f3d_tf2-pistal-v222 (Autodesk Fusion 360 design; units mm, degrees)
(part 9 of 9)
sketch "Sketch209" plane through (-12, 0, 0) normal (-1, 0, 0) x axis (0, -1, 0)
  line L1 (-152.7089, 8.4519) -> (-152.3198, 8.841)
  line L2 (-153.3679, 3.9459) -> (-153.3679, 6.8609)
  line L3 (-156.6179, 2.4459) -> (-154.8679, 2.4459)
  line L4 (-159.3679, 12.5) -> (-159.3679, 5.1959)
  line L5 (-102, 15.5) -> (-156.3679, 15.5)
  line L6 (-99.5, 12) -> (-99.5, 13)
  line L7 (-150.7288, 9.5) -> (-102, 9.5)
  line L8 (-62.1873, 16) -> (-62.1873, 4.4251)
  line L9 (-205.8331, 16) -> (-62.1873, 16)
  line L10 (-221.2152, 0.6179) -> (-205.8331, 16)
  line L11 (-220.6993, -4.9724) -> (-221.2152, 0.6179)
  line L12 (-206.6662, -17.6022) -> (-220.6993, -4.9724)
  line L13 (-206.6662, -40.176) -> (-206.6662, -17.6022)
  curve K1 (-206.6662, -40.176) -> (-240.3598, -109.3449)
  line L14 (-189.1188, -123.2274) -> (-240.3598, -109.3449)
  line L15 (-186.4094, -113.2266) -> (-189.1188, -123.2274)
  line L16 (-189.1513, -106.0289) -> (-186.4094, -113.2266)
  line L17 (-169.5112, -33.2283) -> (-189.2884, -97.8715)
  curve K2 (-169.5112, -33.2283) -> (-143.7253, -13.6797)
  line L18 (-94.4207, -13.6797) -> (-143.7253, -13.6797)
  curve K3 (-94.4207, -13.6797) -> (-62.1781, 2.9716)
  curve K4 (-62.1781, 2.9716) -> (-62.1873, 4.4251)
  curve K5 (-241.1431, -95.8083) -> (-241.1431, -95.8083)
  circle C1 centre (-80, -5) radius 4.5
  arc A1 centre (-150.7288, 7.25) radius 2.25 clockwise from (-152.3198, 8.841) to (-150.7288, 9.5)
  arc A2 centre (-151.1179, 6.8609) radius 2.25 clockwise from (-153.3679, 6.8609) to (-152.7089, 8.4519)
  arc A3 centre (-154.8679, 3.9459) radius 1.5 clockwise from (-153.3679, 3.9459) to (-154.8679, 2.4459)
  arc A4 centre (-156.6179, 5.1959) radius 2.75 clockwise from (-156.6179, 2.4459) to (-159.3679, 5.1959)
  arc A5 centre (-156.3679, 12.5) radius 3 clockwise from (-159.3679, 12.5) to (-156.3679, 15.5)
  arc A6 centre (-102, 13) radius 2.5 clockwise from (-102, 15.5) to (-99.5, 13)
  arc A7 centre (-102, 12) radius 2.5 clockwise from (-99.5, 12) to (-102, 9.5)
  arc A8 centre (-177.9477, -101.7609) radius 11.9891 clockwise from (-189.1513, -106.0289) to (-189.2884, -97.8715)
  circle C2 centre (-133.5549, -4.0047) radius 3.1
  circle C3 centre (-240, -95) radius 3
  dimension "d1660" diameter C3 = 6
extrude "Extrude216" cut sketch "Sketch209" profile of K5 C3 against normal blind 7
chamfer "Chamfer97" distance 1.6
fillet "Fillet249" radius 0.5
sketch "Sketch210" plane through (-12, 0, 0) normal (-1, 0, 0) x axis (0, -1, 0)
  line L1 (-152.7089, 8.4519) -> (-152.3198, 8.841)
  line L2 (-153.3679, 3.9459) -> (-153.3679, 6.8609)
  line L3 (-156.6179, 2.4459) -> (-154.8679, 2.4459)
  line L4 (-159.3679, 12.5) -> (-159.3679, 5.1959)
  line L5 (-102, 15.5) -> (-156.3679, 15.5)
  line L6 (-99.5, 12) -> (-99.5, 13)
  line L7 (-150.7288, 9.5) -> (-102, 9.5)
  line L8 (-62.1873, 16) -> (-62.1873, 4.4251)
  line L9 (-205.8331, 16) -> (-62.1873, 16)
  line L10 (-221.2152, 0.6179) -> (-205.8331, 16)
  line L11 (-220.6993, -4.9724) -> (-221.2152, 0.6179)
  line L12 (-206.6662, -17.6022) -> (-220.6993, -4.9724)
  line L13 (-206.6662, -40.176) -> (-206.6662, -17.6022)
  curve K1 (-206.6662, -40.176) -> (-240.3598, -109.3449)
  line L14 (-189.1188, -123.2274) -> (-240.3598, -109.3449)
  line L15 (-186.4094, -113.2266) -> (-189.1188, -123.2274)
  line L16 (-189.1513, -106.0289) -> (-186.4094, -113.2266)
  line L17 (-169.5112, -33.2283) -> (-189.2884, -97.8715)
  curve K2 (-169.5112, -33.2283) -> (-143.7253, -13.6797)
  line L18 (-94.4207, -13.6797) -> (-143.7253, -13.6797)
  curve K3 (-94.4207, -13.6797) -> (-62.1781, 2.9716)
  curve K4 (-62.1781, 2.9716) -> (-62.1873, 4.4251)
  circle C1 centre (-80, -5) radius 4.5
  arc A1 centre (-150.7288, 7.25) radius 2.25 clockwise from (-152.3198, 8.841) to (-150.7288, 9.5)
  arc A2 centre (-151.1179, 6.8609) radius 2.25 clockwise from (-153.3679, 6.8609) to (-152.7089, 8.4519)
  arc A3 centre (-154.8679, 3.9459) radius 1.5 clockwise from (-153.3679, 3.9459) to (-154.8679, 2.4459)
  arc A4 centre (-156.6179, 5.1959) radius 2.75 clockwise from (-156.6179, 2.4459) to (-159.3679, 5.1959)
  arc A5 centre (-156.3679, 12.5) radius 3 clockwise from (-159.3679, 12.5) to (-156.3679, 15.5)
  arc A6 centre (-102, 13) radius 2.5 clockwise from (-102, 15.5) to (-99.5, 13)
  arc A7 centre (-102, 12) radius 2.5 clockwise from (-99.5, 12) to (-102, 9.5)
  arc A8 centre (-177.9477, -101.7609) radius 11.9891 clockwise from (-189.1513, -106.0289) to (-189.2884, -97.8715)
  circle C2 centre (-133.5549, -4.0047) radius 3.1
  circle C3 centre (-183, -119) radius 1.4
  circle C4 centre (-223.0112, -7.5473) radius 1.4
  circle C5 centre (-161.572, -50.0989) radius 1.4
  circle C6 centre (-115, -20) radius 1.4
  circle C7 centre (-94.3696, -6.8503) radius 1.4
  circle C8 centre (-71.0718, 1.1484) radius 1.4
  circle C9 centre (-210.3179, 3.2924) radius 1.4
  dimension "d1666" diameter C3 = 2.8
  dimension "d1667" diameter C4 = 2.8
  dimension "d1668" diameter C5 = 2.8
  dimension "d1669" diameter C6 = 2.8
  dimension "d1670" diameter C8 = 2.8
  dimension "d1671" diameter C7 = 2.8
  dimension "d1672" diameter C9 = 2.8
extrude "Extrude217" cut sketch "Sketch210" profile of C3 C4 C5 C6 C7 C8 C9 against normal blind 19
extrude "Extrude218" add of existing geometry blind 3
sketch "Sketch211" plane through (-12, 0, 0) normal (-1, 0, 0) x axis (0, -1, 0)
  line L1 (-152.7089, 8.4519) -> (-152.3198, 8.841)
  line L2 (-153.3679, 3.9459) -> (-153.3679, 6.8609)
  line L3 (-156.6179, 2.4459) -> (-154.8679, 2.4459)
  line L4 (-159.3679, 12.5) -> (-159.3679, 5.1959)
  line L5 (-102, 15.5) -> (-156.3679, 15.5)
  line L6 (-99.5, 12) -> (-99.5, 13)
  line L7 (-150.7288, 9.5) -> (-102, 9.5)
  line L8 (-62.1873, 16) -> (-62.1873, 4.4251)
  line L9 (-205.8331, 16) -> (-62.1873, 16)
  line L10 (-221.2152, 0.6179) -> (-205.8331, 16)
  line L11 (-220.6993, -4.9724) -> (-221.2152, 0.6179)
  line L12 (-206.6662, -17.6022) -> (-220.6993, -4.9724)
  line L13 (-206.6662, -40.176) -> (-206.6662, -17.6022)
  curve K1 (-206.6662, -40.176) -> (-240.3598, -109.3449)
  line L14 (-189.1188, -123.2274) -> (-240.3598, -109.3449)
  line L15 (-186.4094, -113.2266) -> (-189.1188, -123.2274)
  line L16 (-189.1513, -106.0289) -> (-186.4094, -113.2266)
  line L17 (-169.5112, -33.2283) -> (-189.2884, -97.8715)
  curve K2 (-169.5112, -33.2283) -> (-143.7253, -13.6797)
  line L18 (-94.4207, -13.6797) -> (-143.7253, -13.6797)
  curve K3 (-94.4207, -13.6797) -> (-62.1781, 2.9716)
  curve K4 (-62.1781, 2.9716) -> (-62.1873, 4.4251)
  curve K5 (-224.1149, -6.6859) -> (-223.0419, -6.1476)
  curve K6 (-184.3513, -118.6339) -> (-184.3513, -118.6339)
  circle C1 centre (-71.0718, 1.1484) radius 1.4
  circle C2 centre (-210.3179, 3.2924) radius 1.4
  circle C3 centre (-94.3696, -6.8503) radius 1.4
  circle C4 centre (-80, -5) radius 4.5
  arc A1 centre (-150.7288, 7.25) radius 2.25 clockwise from (-152.3198, 8.841) to (-150.7288, 9.5)
  arc A2 centre (-151.1179, 6.8609) radius 2.25 clockwise from (-153.3679, 6.8609) to (-152.7089, 8.4519)
  arc A3 centre (-154.8679, 3.9459) radius 1.5 clockwise from (-153.3679, 3.9459) to (-154.8679, 2.4459)
  arc A4 centre (-156.6179, 5.1959) radius 2.75 clockwise from (-156.6179, 2.4459) to (-159.3679, 5.1959)
  arc A5 centre (-156.3679, 12.5) radius 3 clockwise from (-159.3679, 12.5) to (-156.3679, 15.5)
  arc A6 centre (-102, 13) radius 2.5 clockwise from (-102, 15.5) to (-99.5, 13)
  arc A7 centre (-102, 12) radius 2.5 clockwise from (-99.5, 12) to (-102, 9.5)
  arc A8 centre (-177.9477, -101.7609) radius 11.9891 clockwise from (-189.1513, -106.0289) to (-189.2884, -97.8715)
  circle C5 centre (-133.5549, -4.0047) radius 3.1
  circle C6 centre (-210.3179, 3.2924) radius 1.4
  circle C7 centre (-161.572, -50.0989) radius 1.4
  circle C8 centre (-115, -20) radius 1.4
  circle C9 centre (-94.3696, -6.8503) radius 1.4
  circle C10 centre (-71.0718, 1.1484) radius 1.4
  circle C11 centre (-223.0419, -7.5923) radius 3
  circle C12 centre (-210.3179, 3.2924) radius 3
  circle C13 centre (-183, -119) radius 3.0066
  circle C14 centre (-94.3696, -6.8503) radius 3
  circle C15 centre (-71.0718, 1.1484) radius 3
  concentric C6 C12
  concentric C9 C14
  concentric C10 C15
  dimension "d1677" diameter C14 = 6
  dimension "d1678" diameter C15 = 6
  dimension "d1679" diameter C12 = 6
  dimension "d1680" diameter C11 = 6
extrude "Extrude219" cut sketch "Sketch211" profile of C1 C2 C3 C6 K6 C9 C10 C11 C12 C13 C14 C15 against normal blind 7
chamfer "Chamfer98" distance 1.6
chamfer "Chamfer99" distance 1.6
fillet "Fillet250" radius 0.5
sketch "Sketch212" plane through (0, 0, 0) normal (-1, 0, 0) x axis (0, -1, 0)
  line L1 (-235.4811, 5.5) -> (-235.4811, 9.0036)
  line L2 (-227.3196, 5) -> (-234.9811, 5)
  line L3 (-223.1146, 0.1327) -> (-227.3196, 5)
  line L4 (-231.0728, -7.8255) -> (-223.1146, 0.1327)
  line L5 (-231.3905, -7.8255) -> (-231.0728, -7.8255)
  curve K1 (-231.3905, -7.8255) -> (-232.3863, -8.9174)
  line L6 (-232.2171, -10.7508) -> (-232.3863, -8.9174)
  line L7 (-218.6662, -22.9466) -> (-232.2171, -10.7508)
  line L8 (-218.6662, -36.3833) -> (-218.6662, -22.9466)
  curve K2 (-252.0162, -106.1931) -> (-218.6662, -36.3833)
  line L9 (-251.4169, -107.3853) -> (-252.0162, -106.1931)
  line L10 (-235.1318, -111.7973) -> (-251.4169, -107.3853)
  line L11 (-214.7493, -39.6031) -> (-233.9044, -111.0909)
  line L12 (-217, -39) -> (-214.7493, -39.6031)
  line L13 (-217, -17) -> (-217, -39)
  line L14 (-213.8018, -4.3472) -> (-217, -17)
  line L15 (-207.5956, -4.3472) -> (-213.8018, -4.3472)
  line L16 (-215.7362, -34.7285) -> (-207.5956, -4.3472)
  line L17 (-213.5968, -35.3017) -> (-215.7362, -34.7285)
  line L18 (-201.3197, 10.517) -> (-213.5968, -35.3017)
  line L19 (-201.6902, 11) -> (-201.3197, 10.517)
  line L20 (-211.7473, 11) -> (-201.6902, 11)
  line L21 (-212.6009, 10.6464) -> (-211.7473, 11)
  line L22 (-217.4321, 5.8152) -> (-212.6009, 10.6464)
  line L23 (-220.6186, 9.5036) -> (-217.4321, 5.8152)
  line L24 (-234.9811, 9.5036) -> (-220.6186, 9.5036)
  line L25 (-207, -1.3414) -> (-211.7301, -1.3414)
  line L26 (-207.5956, -4.3472) -> (-207, -1.3414)
  line L27 (-211.2707, 0.9774) -> (-211.7301, -1.3414)
  line L28 (-203.8758, 0.9774) -> (-211.2707, 0.9774)
  line L29 (-217.4482, -1.3414) -> (-211.7301, -1.3414)
  line L30 (-217.4482, 3.6482) -> (-217.4482, -1.3414)
  line L31 (-214.5891, 3.6482) -> (-217.4482, 3.6482)
  line L32 (-214.5891, 0.9774) -> (-214.5891, 3.6482)
  line L33 (-211.2707, 0.9774) -> (-214.5891, 0.9774)
  circle C1 centre (-210.3179, 3.2924) radius 1.4
  circle C2 centre (-223.0112, -7.5473) radius 1.4
  circle C3 centre (-240, -95) radius 1.4
  arc A1 centre (-234.9811, 9.0036) radius 0.5 clockwise from (-235.4811, 9.0036) to (-234.9811, 9.5036)
  arc A2 centre (-234.9811, 5.5) radius 0.5 clockwise from (-234.9811, 5) to (-235.4811, 5.5)
  arc A3 centre (-234.8703, -110.8321) radius 1 clockwise from (-233.9044, -111.0909) to (-235.1318, -111.7973)
  point P28 (-207.5956, -4.3472)
  point P39 (-207.5956, -4.3472)
  point P41 (-203.8758, 0.9774)
  parallel L2 L25
  coincident P28 P39
  parallel L26 L27
  coincident L18 P41
  parallel L25 L28
  parallel L25 L29
  perpendicular L25 L30
  perpendicular L30 L31
  perpendicular L28 L32
  perpendicular L32 L33
extrude "Extrude220" new body sketch "Sketch212" profile of L16 L17 L18 L25 L26 L27 L28 L29 L30 L31 L32 L33 distance -5
combine "Combine161"
combine "Combine162"
move_face "MoveFace306"
move_face "MoveFace307"
move_face "MoveFace308"
move_face "MoveFace309"
move_face "MoveFace310"
move_face "MoveFace311"
move_face "MoveFace312"
move_face "MoveFace313"
move_face "MoveFace314"
move_face "MoveFace315"
move_face "MoveFace316"
sketch "Sketch213" plane through (-4.8, 0, 0) normal (-1, 0, 0) x axis (0, -1, 0)
  line L1 (-207, -1.3414) -> (-217.5482, -1.3414)
  line L2 (-207.5956, -4.3472) -> (-207, -1.3414)
  line L3 (-215.7362, -34.7285) -> (-207.5956, -4.3472)
  line L4 (-213.5968, -35.3017) -> (-215.7362, -34.7285)
  line L5 (-203.8758, 0.9774) -> (-213.5968, -35.3017)
  line L6 (-214.4891, 0.9774) -> (-203.8758, 0.9774)
  line L7 (-214.4891, 3.7482) -> (-214.4891, 0.9774)
  line L8 (-217.5482, 3.7482) -> (-214.4891, 3.7482)
  line L9 (-217.5482, -1.3414) -> (-217.5482, 3.7482)
  line L10 (-211.126, -31.7822) -> (-212.5514, -31.4003)
  line L11 (-212.1714, -35.6837) -> (-215.7362, -34.7285)
  line L12 (-211.126, -31.7822) -> (-212.1714, -35.6837)
  point P11 (-212.5514, -31.4003)
  point P5 (-215.7362, -34.7285)
  point P12 (-215.7362, -34.7285)
  coincident L5 P11
  perpendicular L5 L10
  coincident P5 P12
  perpendicular L5 L11
  perpendicular L10 L12
extrude "Extrude221" add sketch "Sketch213" profile of L5 L10 L11 L12 against normal blind 9.6
move_face "MoveFace317"
fillet "Fillet251" radius 1
sketch "Sketch214" plane through (0, 0, 24.2) normal (0, 0, 1) x axis (-1, 0, 0)
  line L1 (2.8, -206.5) -> (2.3, -207)
  line L2 (2.8, -188.1902) -> (2.8, -206.5)
  line L3 (-2.8, -188.1902) -> (2.8, -188.1902)
  line L4 (-2.8, -206.5) -> (-2.8, -188.1902)
  line L5 (-2.3, -207) -> (-2.8, -206.5)
  line L6 (2.3, -207) -> (-2.3, -207)
  circle C1 centre (0, -202) radius 1.4
  circle C2 centre (0, -192) radius 1.4
  dimension "d1693" diameter C2 = 2.8
  dimension "d1694" diameter C1 = 2.8
extrude "Extrude222" cut sketch "Sketch214" profile of C1 C2 along normal blind 3 and against normal blind 8
chamfer "Chamfer100" distance 1.6
move_face "MoveFace318"
sketch "Sketch215" plane through (2.8, 0, 0) normal (1, 0, 0) x axis (0, 1, 0)
  line L1 (206.5, 24.2) -> (206.5, 11.142)
  line L2 (188.1902, 24.2) -> (206.5, 24.2)
  line L3 (188.1902, 17.483) -> (188.1902, 24.2)
  line L4 (154, 17.483) -> (188.1902, 17.483)
  line L5 (154, 11.142) -> (154, 17.483)
  line L6 (206.5, 11.142) -> (154, 11.142)
  curve K1 (158.3983, 11.142) -> (153, 13)
  point P10 (158.3983, 11.142)
  coincident L6 P10
extrude "Extrude223" cut sketch "Sketch215" profile of L5 L6 K1 against normal blind 8
fillet "Fillet252" radius 0.5
sketch "Sketch216" plane through (-14, 0, 0) normal (-1, 0, 0) x axis (0, -1, 0)
  line L1 (-191.5572, -110.665) -> (-193.4854, -117.0054)
  line L2 (-192.5941, -101.8429) -> (-191.421, -108.319)
  line L3 (-166.2531, -15.2274) -> (-192.5941, -101.8429)
  line L4 (-205.6474, -12) -> (-168.645, -12)
  line L5 (-208.7895, -33.7396) -> (-208.146, -14.4168)
  line L6 (-241.0868, -103.8801) -> (-208.7895, -33.7396)
  line L7 (-193.4854, -117.0054) -> (-241.0868, -103.8801)
  curve K1 (-242.0451, -97.1949) -> (-242.0451, -97.1949)
  arc A1 centre (-196.3409, -109.2102) radius 5 clockwise from (-191.421, -108.319) to (-191.5572, -110.665)
  arc A2 centre (-168.645, -14.5) radius 2.5 clockwise from (-168.645, -12) to (-166.2531, -15.2274)
  arc A3 centre (-205.6474, -14.5) radius 2.5 clockwise from (-208.146, -14.4168) to (-205.6474, -12)
  circle C1 centre (-205.3592, -68.1791) radius 13.3064
extrude "Extrude224" cut sketch "Sketch216" profile of L6 K1 against normal blind 10
fillet "Fillet253" radius 0.5
fillet "Fillet254" radius 0.5
sketch "Sketch217" plane through (0, 0, 0) normal (1, 0, 0) x axis (0, 1, 0)
  line L1 (102.1605, -26.431) -> (156.5305, -15.1522)
sketch "Sketch218" plane through (0, 86.8357, 31.9547) normal (0, -0.9385, -0.3453) x axis (1, 0, 0)
  line L1 (0, -82.7553) -> (0, -56.5218)
  line L2 (5.5, -82.7553) -> (0, -82.7553)
  line L3 (5.5, -56.5218) -> (5.5, -82.7553)
  line L4 (0, -56.5218) -> (5.5, -56.5218)
  circle C1 centre (0, -61) radius 2.5
  point P6 (0, -61)
  coincident L1 P6
  dimension "d1710" diameter C1 = 5
move_face "MoveFace319"
sketch "Sketch219" plane through (-8, 0, 0) normal (-1, 0, 0) x axis (0, -1, 0)
  curve K1 (-125.8981, -20.4248) -> (-122.5933, -16.1797)
  curve K2 (-163.7067, -39.835) -> (-159.6203, -38.6321)
  line L1 (-170.614, -62.4121) -> (-163.7067, -39.835)
  line L2 (-165.2582, -58.8926) -> (-170.614, -62.4121)
  line L3 (-145.3157, -58.346) -> (-155.3973, -56.7622)
  line L4 (-108.7016, -20.2262) -> (-117.7685, -44.8652)
  line L5 (-122.5933, -16.1797) -> (-105.9313, -16.1797)
  circle C1 centre (-161.572, -50.0989) radius 1.4
  circle C2 centre (-114, -19) radius 1.4
  arc A1 centre (-138.3458, -37.7027) radius 21.2949 clockwise from (-125.8981, -20.4248) to (-159.6203, -38.6321)
  arc A2 centre (-157.5699, -70.5926) radius 14 clockwise from (-165.2582, -58.8926) to (-155.3973, -56.7622)
  arc A3 centre (-138.3458, -37.7027) radius 21.7882 clockwise from (-117.7685, -44.8652) to (-145.3157, -58.346)
  arc A4 centre (-99.3169, -23.6797) radius 10 clockwise from (-108.7016, -20.2262) to (-105.9313, -16.1797)
  circle C3 centre (-114, -19) radius 3
  circle C4 centre (-161.572, -50.0989) radius 3
  concentric C2 C3
  concentric C1 C4
  dimension "d1711" diameter C3 = 6
  dimension "d1712" diameter C4 = 6
extrude "Extrude225" cut sketch "Sketch219" profile of C1 C2 L5 C3 C4 along normal blind 12 and against normal blind 3
chamfer "Chamfer101" distance 1.6
fillet "Fillet255" radius 0.5
sweep "Sweep3" sketch "Sketch218" TwistAngle 0 TaperAngle 0
sketch "Sketch220" plane through (0, 86.8357, 31.9547) normal (0, -0.9385, -0.3453) x axis (1, 0, 0)
  line L1 (0, -82.7553) -> (0, -63.5)
  line L2 (5.5, -82.7553) -> (0, -82.7553)
  line L3 (5.5, -56.5218) -> (5.5, -82.7553)
  line L4 (0, -56.5218) -> (5.5, -56.5218)
  line L5 (0, -58.5) -> (0, -56.5218)
  arc A1 centre (0, -61) radius 2.5 clockwise from (0, -58.5) to (0, -63.5)
  circle C1 centre (0, -61) radius 3.5
  concentric A1 C1
  dimension "d1726" diameter C1 = 7
sweep "Sweep4" sketch "Sketch220" TwistAngle 0 TaperAngle 0
copy_paste_bodies "CopyPasteBodies16"
move "Move106"
combine "Combine163"
move_face "MoveFace320"
combine "Combine164"
combine "Combine165"
fillet "Fillet256" radius 0.5
move_face "MoveFace321"
fillet "Fillet257" radius 0.5
sketch "Sketch221" plane through (-15, 0, 0) normal (-1, 0, 0) x axis (0, -1, 0)
  line L1 (-97.1247, 4.9996) -> (-97.1319, 7.0581)
  line L2 (-156.764, 1.7923) -> (-100.1143, 1.9892)
  line L3 (-160.0253, 12.4736) -> (-160.0253, 5.0422)
  line L4 (-101.9643, 15.9736) -> (-156.5253, 15.9736)
  line L5 (-97.1319, 7.0581) -> (-99.0822, 13.8065)
  line L6 (-101.5272, -6.2081) -> (-225.7107, -6.2081)
  curve K1 (-101.5272, -6.2081) -> (-99.7709, -5.1649)
  curve K2 (-99.7709, -5.1649) -> (-70.1883, 6.8275)
  line L7 (-62.5, 6.8275) -> (-70.1883, 6.8275)
  line L8 (-60.5, 19.7929) -> (-60.5, 8.8275)
  line L9 (-205.9389, 19.7929) -> (-60.5, 19.7929)
  line L10 (-225.7107, -6.2081) -> (-205.9389, 19.7929)
  line L11 (-211.5034, -4.5867) -> (-203.027, 17.9284)
  line L12 (-209.9848, -4.5867) -> (-211.5034, -4.5867)
  line L13 (-201.5083, 17.9284) -> (-209.9848, -4.5867)
  line L14 (-203.027, 17.9284) -> (-201.5083, 17.9284)
  arc A1 centre (-100.1247, 4.9892) radius 3 clockwise from (-97.1247, 4.9996) to (-100.1143, 1.9892)
  arc A2 centre (-156.7753, 5.0422) radius 3.25 clockwise from (-156.764, 1.7923) to (-160.0253, 5.0422)
  arc A3 centre (-156.5253, 12.4736) radius 3.5 clockwise from (-160.0253, 12.4736) to (-156.5253, 15.9736)
  arc A4 centre (-101.9643, 12.9736) radius 3 clockwise from (-101.9643, 15.9736) to (-99.0822, 13.8065)
  arc A5 centre (-62.5, 8.8275) radius 2 clockwise from (-60.5, 8.8275) to (-62.5, 6.8275)
  horizontal L12
  parallel L11 L13
  parallel L12 L14
extrude "Extrude226" new body sketch "Sketch221" profile of L11 L12 L13 L14 along normal blind 2
fillet "Fillet258" radius 0.5
move "Move107"
path_pattern "PathPattern3" PathPatternDelta 52.076
mirror "Mirror46" mirrorStitchTolerance 0.1
combine "Combine166"
fillet "Fillet259" radius 0.5
delete_face "DeleteFace159"
delete_face "DeleteFace160"
offset_faces "OffsetFaces34" distance 2
chamfer "Chamfer102" distance 3
fillet "Fillet260" radius 5
sketch "Sketch222" plane through (12, 0, 0) normal (1, 0, 0) x axis (0, 1, 0)
  line L1 (99.5, 13) -> (99.5, 12)
  line L2 (156.3679, 15.5) -> (102, 15.5)
  line L3 (159.3679, 5.1959) -> (159.3679, 12.5)
  line L4 (154.8679, 2.4459) -> (156.6179, 2.4459)
  line L5 (153.3679, 6.8609) -> (153.3679, 3.9459)
  line L6 (152.3198, 8.841) -> (152.7089, 8.4519)
  line L7 (102, 9.5) -> (150.7288, 9.5)
  curve K1 (62.1873, 4.4251) -> (62.1781, 2.9716)
  curve K2 (62.1781, 2.9716) -> (94.4207, -13.6797)
  line L8 (143.7253, -13.6797) -> (94.4207, -13.6797)
  curve K3 (143.7253, -13.6797) -> (169.5112, -33.2283)
  line L9 (189.3472, -98.0638) -> (169.5112, -33.2283)
  line L10 (189.1188, -123.2274) -> (185.6444, -110.403)
  line L11 (240.3598, -109.3449) -> (189.1188, -123.2274)
  curve K4 (240.3598, -109.3449) -> (206.6662, -40.176)
  line L12 (206.6662, -17.6022) -> (206.6662, -40.176)
  line L13 (220.6993, -4.9724) -> (206.6662, -17.6022)
  line L14 (221.2152, 0.6179) -> (220.6993, -4.9724)
  line L15 (205.8331, 16) -> (221.2152, 0.6179)
  line L16 (62.1873, 16) -> (205.8331, 16)
  line L17 (62.1873, 4.4251) -> (62.1873, 16)
  line L18 (171.6846, -117.0944) -> (196.1305, -110.4714)
  line L19 (167, -101) -> (171.6846, -117.0944)
  line L20 (192.3892, -94.1214) -> (167, -101)
  line L21 (196.1305, -110.4714) -> (192.3892, -94.1214)
  circle C1 centre (80, -5) radius 4.5
  arc A1 centre (102, 12) radius 2.5 clockwise from (102, 9.5) to (99.5, 12)
  arc A2 centre (102, 13) radius 2.5 clockwise from (99.5, 13) to (102, 15.5)
  arc A3 centre (156.3679, 12.5) radius 3 clockwise from (156.3679, 15.5) to (159.3679, 12.5)
  arc A4 centre (156.6179, 5.1959) radius 2.75 clockwise from (159.3679, 5.1959) to (156.6179, 2.4459)
  arc A5 centre (154.8679, 3.9459) radius 1.5 clockwise from (154.8679, 2.4459) to (153.3679, 3.9459)
  arc A6 centre (151.1179, 6.8609) radius 2.25 clockwise from (152.7089, 8.4519) to (153.3679, 6.8609)
  arc A7 centre (150.7288, 7.25) radius 2.25 clockwise from (150.7288, 9.5) to (152.3198, 8.841)
  arc A8 centre (180.741, -100.6968) radius 9 clockwise from (189.3472, -98.0638) to (184.9634, -108.6448)
  arc A9 centre (176.9575, -112.7565) radius 9 clockwise from (184.9634, -108.6448) to (185.6444, -110.403)
  circle C2 centre (133.5549, -4.0047) radius 3.1
  perpendicular L10 L18
  perpendicular L10 L20
split "Split63" bodies "Body_R", "Bod7_L"
mirror "Mirror47" mirrorStitchTolerance 0.1 bodies "Body_R (2)"
combine "Combine167" bodies "Body_R (2)"
combine "Combine168"
fillet "Fillet261" radius 7.5
move_face "MoveFace322"
move_face "MoveFace323"
move_face "MoveFace324"
combine "Combine169"
move_face "MoveFace325"
move_face "MoveFace326" TranslateX 0 TranslateY -1 TranslateZ 4
fillet "Fillet262" radius 3.25
sketch "Sketch223" plane through (0, 192.6025, 51.6077) normal (0, 0.9659, 0.2588) x axis (-1, 0, 0)
  line L1 (4.8, -82.5706) -> (-4.8, -82.5706)
  line L2 (4.8, -57.9288) -> (4.8, -82.5706)
  line L3 (-4.8, -57.9288) -> (4.8, -57.9288)
  line L4 (-4.8, -82.5706) -> (-4.8, -57.9288)
  line L5 (6, -58.6622) -> (-4.8, -58.6622)
  point P6 (-4.8, -58.6622)
  coincident L4 P6
  perpendicular L2 L5
extrude "Extrude227" add sketch "Sketch223" profile of L1 L2 L4 L5 along normal blind 1
fillet "Fillet263" radius 69
move_face "MoveFace327"
move_face "MoveFace328"
move_face "MoveFace329"
delete_face "DeleteFace161"
delete_face "DeleteFace162"
fillet "Fillet264" radius 0.75
move_face "MoveFace330"
move_face "MoveFace331"
fillet "Fillet265" radius 0.4
offset_faces "OffsetFaces35" distance 0.2
offset_faces "OffsetFaces36" distance 0.1
delete_face "DeleteFace163"
offset_faces "OffsetFaces37" distance 1
move_face "MoveFace332"
fillet "Fillet266" radius 1.5
move_face "MoveFace333"
move_face "MoveFace334"
fillet "Fillet267" radius 0.5
move_face "MoveFace335"
move_face "MoveFace336"
move_face "MoveFace337"
delete_face "DeleteFace164"
fillet "Fillet268" radius 0.5
sketch "Sketch224" plane through (-4.8, 0, 0) normal (-1, 0, 0) x axis (0, -1, 0)
  line L1 (-210.0622, -28.3169) -> (-210.9938, -31.7938)
  line L2 (-211.4844, -27.4182) -> (-210.4158, -27.7046)
  line L3 (-203.8758, 0.9774) -> (-211.4844, -27.4182)
  line L4 (-214.4891, 0.9774) -> (-203.8758, 0.9774)
  line L5 (-214.4891, 3.7482) -> (-214.4891, 0.9774)
  line L6 (-217.5482, 3.7482) -> (-214.4891, 3.7482)
  line L7 (-217.5482, -1.3414) -> (-217.5482, 3.7482)
  line L8 (-207, -1.3414) -> (-217.5482, -1.3414)
  line L9 (-207.5956, -4.3472) -> (-207, -1.3414)
  line L10 (-207.6119, -4.4082) -> (-207.5956, -4.3472)
  line L11 (-208.6472, -4.4082) -> (-207.6119, -4.4082)
  line L12 (-211.9099, -16.5847) -> (-208.6472, -4.4082)
  line L13 (-213, -4.4082) -> (-208.6472, -4.4082)
  line L14 (-213.6978, -4.4082) -> (-213, -4.4082)
  line L15 (-214.9355, -9.0273) -> (-213.6978, -4.4082)
  line L16 (-212.3934, -18.4984) -> (-214.9355, -9.0273)
  arc A1 centre (-211.4768, -31.6644) radius 0.5 clockwise from (-210.9938, -31.7938) to (-211.5936, -32.1506)
  arc A2 centre (-210.5452, -28.1875) radius 0.5 clockwise from (-210.4158, -27.7046) to (-210.0622, -28.3169)
  arc A3 centre (-145.261, -34.4433) radius 69 clockwise from (-213.9733, -28.1494) to (-211.9099, -16.5847)
  arc A4 centre (-210.8341, -28.9906) radius 3.25 clockwise from (-211.5936, -32.1506) to (-213.9733, -28.1494)
  point P17 (-208.6472, -4.4082)
  point P22 (-208.6472, -4.4082)
  point P26 (-212.3934, -18.4984)
  coincident P17 P22
  parallel L11 L13
  parallel L13 L14
  parallel L12 L15
  coincident A3 P26
extrude "Extrude228" add sketch "Sketch224" profile of L12 A3 L13 L14 L15 L16 against normal blind 9.6
delete_face "DeleteFace165"
move_face "MoveFace338"
fillet "Fillet269" radius 0.5
delete_face "DeleteFace166"
move_face "MoveFace339"
fillet "Fillet270" radius 0.5
sketch "Sketch225" plane through (0, 0, 0) normal (1, 0, 0) x axis (0, 1, 0)
  line L1 (168, 20.7) -> (168, 19.6503)
  line L2 (187.5, 20.7) -> (168, 20.7)
  line L3 (188, 21.2) -> (187.5, 20.7)
  line L4 (188, 23.3) -> (188, 21.2)
  line L5 (187.5, 23.8) -> (188, 23.3)
  line L6 (61.1873, 23.8) -> (187.5, 23.8)
  line L7 (61.1873, 21.4503) -> (61.1873, 23.8)
  line L8 (59.1873, 21.4503) -> (61.1873, 21.4503)
  line L9 (59.1873, 19.1503) -> (59.1873, 21.4503)
  line L10 (167.5, 19.1503) -> (59.1873, 19.1503)
  line L11 (59.1873, 5.7503) -> (147.372, 5.7503)
  line L12 (59.1873, 19.1503) -> (167.5, 19.1503)
  arc A1 centre (167.5, 19.6503) radius 0.5 clockwise from (168, 19.6503) to (167.5, 19.1503)
  circle C1 centre (146.168, 19.1503) radius 0.5
  circle C2 centre (146.1448, 5.7503) radius 0.5
  point P18 (146.168, 19.1503)
  point P19 (146.1448, 5.7503)
  coincident L12 P18
  coincident L11 P19
  dimension "d1783" diameter C2 = 1
  dimension "d1784" diameter C1 = 1
extrude "Extrude229" new body sketch "Sketch225" profile of L10 L11 L12 C1 C2 against normal blind 3
mirror "Mirror48" mirrorStitchTolerance 0.1
combine "Combine170"
combine "Combine171"
sketch "Sketch226" plane through (-12, 0, 0) normal (-1, 0, 0) x axis (0, -1, 0)
  line L1 (-169.5112, -33.2283) -> (-189.2884, -97.8715)
  curve K1 (-169.5112, -33.2283) -> (-143.7253, -13.6797)
  line L2 (-94.4207, -13.6797) -> (-143.7253, -13.6797)
  curve K2 (-94.4207, -13.6797) -> (-62.1781, 2.9716)
  curve K3 (-62.1781, 2.9716) -> (-62.1873, 4.4251)
  line L3 (-62.1873, 16) -> (-62.1873, 4.4251)
  line L4 (-205.8331, 16) -> (-62.1873, 16)
  line L5 (-221.2152, 0.6179) -> (-205.8331, 16)
  line L6 (-220.6993, -4.9724) -> (-221.2152, 0.6179)
  line L7 (-206.6662, -17.6022) -> (-220.6993, -4.9724)
  line L8 (-206.6662, -40.176) -> (-206.6662, -17.6022)
  curve K4 (-206.6662, -40.176) -> (-240.3598, -109.3449)
  line L9 (-189.1188, -123.2274) -> (-240.3598, -109.3449)
  line L10 (-186.4094, -113.2266) -> (-189.1188, -123.2274)
  line L11 (-189.1513, -106.0289) -> (-186.4094, -113.2266)
  line L12 (-152.7089, 8.4519) -> (-152.3198, 8.841)
  line L13 (-153.3679, 3.9459) -> (-153.3679, 6.8609)
  line L14 (-156.6179, 2.4459) -> (-154.8679, 2.4459)
  line L15 (-159.3679, 12.5) -> (-159.3679, 5.1959)
  line L16 (-102, 15.5) -> (-156.3679, 15.5)
  line L17 (-99.5, 12) -> (-99.5, 13)
  line L18 (-150.7288, 9.5) -> (-102, 9.5)
  line L19 (-193.24, -112.6221) -> (-189.9351, -97.8715)
  line L20 (-165.1003, -120.2459) -> (-193.24, -112.6221)
  line L21 (-160.4733, -103.1674) -> (-165.1003, -120.2459)
  line L22 (-187.8052, -93.0238) -> (-160.4733, -103.1674)
  line L23 (-187.8052, -93.0238) -> (-189.9351, -97.8715)
  arc A1 centre (-177.9477, -101.7609) radius 11.9891 clockwise from (-189.1513, -106.0289) to (-189.2884, -97.8715)
  circle C1 centre (-71.0718, 1.1484) radius 3.5
  circle C2 centre (-133.5549, -4.0047) radius 3.1
  arc A2 centre (-150.7288, 7.25) radius 2.25 clockwise from (-152.3198, 8.841) to (-150.7288, 9.5)
  arc A3 centre (-151.1179, 6.8609) radius 2.25 clockwise from (-153.3679, 6.8609) to (-152.7089, 8.4519)
  arc A4 centre (-154.8679, 3.9459) radius 1.5 clockwise from (-153.3679, 3.9459) to (-154.8679, 2.4459)
  arc A5 centre (-156.6179, 5.1959) radius 2.75 clockwise from (-156.6179, 2.4459) to (-159.3679, 5.1959)
  arc A6 centre (-156.3679, 12.5) radius 3 clockwise from (-159.3679, 12.5) to (-156.3679, 15.5)
  arc A7 centre (-102, 13) radius 2.5 clockwise from (-102, 15.5) to (-99.5, 13)
  arc A8 centre (-102, 12) radius 2.5 clockwise from (-99.5, 12) to (-102, 9.5)
  circle C3 centre (-80, -5) radius 4.5
  circle C4 centre (-210.3179, 3.2924) radius 3.5
  circle C5 centre (-94.3696, -6.8503) radius 3.5
  point P49 (-187.8052, -93.0238)
  perpendicular L10 L20
  perpendicular L20 L21
  coincident L1 P49
split "Split64" bodies "Body_R", "Bod7_L"
mirror "Mirror49" mirrorStitchTolerance 0.1 bodies "Body_R (2)"
combine "Combine172" bodies "Body_R (2)"
combine "Combine173" bodies "Body_R"
delete_face "DeleteFace167"
remove_body "RemoveBody94"
delete_face "DeleteFace168"
fillet "Fillet271" radius 1.65
move_face "MoveFace340"
sketch "Sketch227" plane through (0, 45.6214, -167.8868) normal (0, 0.2622, -0.965) x axis (-1, 0, 0)
  line L1 (-9.2, 161.7683) -> (-9.2, 188.1258)
  line L2 (-8.4, 160.3469) -> (-8.7607, 160.7076)
  line L3 (-8.4, 157.7469) -> (-8.4, 160.3469)
  line L4 (4.4, 153.7469) -> (-4.4, 153.7469)
  line L5 (8.4, 160.3469) -> (8.4, 157.7469)
  line L6 (8.7607, 160.7076) -> (8.4, 160.3469)
  line L7 (9.2, 188.1258) -> (9.2, 161.7683)
  line L8 (8.4, 189.5471) -> (8.7607, 189.1864)
  line L9 (8.4, 192.1471) -> (8.4, 189.5471)
  line L10 (-4.4, 196.1472) -> (4.4, 196.1472)
  line L11 (-8.4, 189.5471) -> (-8.4, 192.1471)
  line L12 (-8.7607, 189.1864) -> (-8.4, 189.5471)
  line L13 (6.75, 157.4469) -> (6.75, 192.4471)
  line L14 (-4.75, 155.4469) -> (4.75, 155.4469)
  line L15 (-6.75, 192.4471) -> (-6.75, 157.4469)
  line L16 (4.75, 194.4471) -> (-4.75, 194.4471)
  line L17 (6.8009, 155.7546) -> (-6.75, 155.7546)
  line L18 (6.8009, 194.1394) -> (6.8009, 155.7546)
  line L19 (-6.75, 194.1394) -> (6.8009, 194.1394)
  line L20 (-6.75, 155.7546) -> (-6.75, 194.1394)
  line L21 (6.8009, 194.1394) -> (-6.75, 155.7546)
  line L22 (-6.75, 194.1394) -> (6.8009, 155.7546)
  closed curve K1 centre (-7.7, 188.1258)
  closed curve K2 centre (-7.7, 161.7683)
  closed curve K3 centre (-4.4, 157.7469)
  closed curve K4 centre (4.4, 157.7469)
  closed curve K5 centre (7.7, 161.7683)
  closed curve K6 centre (7.7, 188.1258)
  closed curve K7 centre (4.4, 192.1471)
  closed curve K8 centre (-4.4, 192.1471)
  closed curve K9 centre (4.75, 157.4469)
  closed curve K10 centre (-4.75, 157.4469)
  closed curve K11 centre (-4.75, 192.4471)
  closed curve K12 centre (4.75, 192.4471)
  point P46 (0.0255, 174.947)
  horizontal L17
  perpendicular L17 L18
  parallel L17 L19
  parallel L18 L20
  coincident L21 P46
  coincident L22 P46
extrude "Extrude230" new body sketch "Sketch227" profile of L13 K9 K10 L15 K11 K12 L17 L18 L19 L20 against normal blind 8
fillet "Fillet272" radius 3
move_face "MoveFace341"
move_face "MoveFace342"
move_face "MoveFace343" RotateAngle 12
chamfer "Chamfer103" distance 2
move_face "MoveFace344"
move "Move108"
move_face "MoveFace345"
move "Move109"
move_face "MoveFace346" RotateAngle 3
delete_face "DeleteFace169"
delete_face "DeleteFace170"
sketch "Sketch228" plane through (0, 0, 0) normal (1, 0, 0) x axis (0, 1, 0)
  line L1 (59.1873, 5.7503) -> (145.6448, 5.7503)
  line L2 (59.1873, 3.4503) -> (59.1873, 5.7503)
  line L3 (61.1873, 3.4503) -> (59.1873, 3.4503)
  line L4 (61.1873, 0.9865) -> (61.1873, 3.4503)
  line L5 (61.1873, 0.9865) -> (61.758, -0.8346)
  curve K1 (94.4938, -16.1797) -> (61.758, -0.8346)
  line L6 (99.3169, -16.1797) -> (94.4938, -16.1797)
  line L7 (106.5444, -21.6032) -> (106.3554, -21.0896)
  curve K2 (106.5444, -21.6032) -> (107.1152, -21.9201)
  line L8 (110.3904, -21.2407) -> (107.1152, -21.9201)
  line L9 (110.7357, -22.1791) -> (110.3904, -21.2407)
  line L10 (141.6921, -15.7573) -> (110.7357, -22.1791)
  curve K3 (141.6921, -15.7573) -> (142.0605, -15.097)
  curve K4 (141.7435, -14.4954) -> (142.0605, -15.097)
  curve K5 (137.9113, -11.6209) -> (141.7435, -14.4954)
  line L11 (147.5434, 4.7806) -> (139.9456, 2.0072)
  curve K6 (147.5434, 4.7806) -> (147.372, 5.7503)
  line L12 (146.6448, 5.7503) -> (147.372, 5.7503)
  line L13 (146, 18.2099) -> (140.716, 18.2099)
  line L14 (146, 20.0099) -> (140.716, 20.0099)
  circle C1 centre (71.0718, 1.1484) radius 1.4
  circle C2 centre (94.3696, -6.8503) radius 1.4
  circle C3 centre (114, -19) radius 1.4
  circle C4 centre (80, -5) radius 4
  arc A1 centre (99.3169, -23.6797) radius 7.5 clockwise from (99.3169, -16.1797) to (106.3554, -21.0896)
  arc A2 centre (133.5549, -4.0047) radius 8.7741 clockwise from (137.9113, -11.6209) to (139.9456, 2.0072)
  arc A3 centre (146.1448, 5.7503) radius 0.5 clockwise from (145.6448, 5.7503) to (146.6448, 5.7503)
  circle C5 centre (146, 19.1099) radius 0.9
  circle C6 centre (140.716, 19.1099) radius 0.9
  point P32 (140.716, 18.2099)
  point P33 (146, 18.2099)
  point P34 (140.716, 20.0099)
  point P35 (146, 20.0099)
  coincident C6 P32
  coincident C5 P33
  tangent C5 L13
  horizontal L13
  coincident C6 P34
  coincident C5 P35
  tangent C5 L14
  horizontal L14
  dimension "d1800" diameter C6 = 1.8
  dimension "d1801" diameter C5 = 1.8
delete_face "DeleteFace171"
extrude "Extrude231" new body sketch "Sketch228" profile of C5 C6 L13 L14 against normal blind 4
mirror "Mirror50" mirrorStitchTolerance 0.1
combine "Combine174"
combine "Combine175"
split "Split65"
move "Move110"
delete_face "DeleteFace172"
delete_face "DeleteFace173"
chamfer "Chamfer104" distance 1
delete_face "DeleteFace174"
delete_face "DeleteFace175"
delete_face "DeleteFace176"
move_face "MoveFace347"
move_face "MoveFace348"
delete_face "DeleteFace177"
move_face "MoveFace349"
delete_face "DeleteFace178"
move_face "MoveFace350"
delete_face "DeleteFace179"
sketch "Sketch229" plane through (-4.8, 0, 0) normal (-1, 0, 0) x axis (0, -1, 0)
  line L1 (-212.8761, -1.3414) -> (-217.5482, -1.3414)
  line L2 (-214.9355, -9.0273) -> (-212.8761, -1.3414)
  line L3 (-212.3934, -18.4984) -> (-214.9355, -9.0273)
  line L4 (-210.1588, -28.2911) -> (-210.6589, -30.1576)
  line L5 (-211.4844, -27.4182) -> (-210.5123, -27.6787)
  line L6 (-203.8758, 0.9774) -> (-211.4844, -27.4182)
  line L7 (-214.4891, 0.9774) -> (-203.8758, 0.9774)
  line L8 (-214.4891, 3.7482) -> (-214.4891, 0.9774)
  line L9 (-217.5482, 3.7482) -> (-214.4891, 3.7482)
  line L10 (-217.5482, -1.3414) -> (-217.5482, 3.7482)
  arc A1 centre (-145.261, -34.4433) radius 69 clockwise from (-213.9733, -28.1494) to (-212.3934, -18.4984)
  arc A2 centre (-210.8341, -28.9906) radius 3.25 clockwise from (-213.7157, -30.4936) to (-213.9733, -28.1494)
  arc A3 centre (-212.2527, -29.7305) radius 1.65 clockwise from (-210.6589, -30.1576) to (-213.7157, -30.4936)
  arc A4 centre (-210.6418, -28.1617) radius 0.5 clockwise from (-210.5123, -27.6787) to (-210.1588, -28.2911)
  circle C1 centre (-209.4687, -5.1844) radius 1.4
  dimension "d1807" diameter C1 = 2.8
extrude "Extrude232" cut sketch "Sketch229" profile of C1 along normal blind 13 and against normal blind 12
sketch "Sketch230" plane through (-4.8, 0, 0) normal (-1, 0, 0) x axis (0, -1, 0)
  line L1 (-212.8761, -1.3414) -> (-217.5482, -1.3414)
  line L2 (-214.9355, -9.0273) -> (-212.8761, -1.3414)
  line L3 (-212.3934, -18.4984) -> (-214.9355, -9.0273)
  line L4 (-210.1588, -28.2911) -> (-210.6589, -30.1576)
  line L5 (-211.4844, -27.4182) -> (-210.5123, -27.6787)
  line L6 (-203.8758, 0.9774) -> (-211.4844, -27.4182)
  line L7 (-214.4891, 0.9774) -> (-203.8758, 0.9774)
  line L8 (-214.4891, 3.7482) -> (-214.4891, 0.9774)
  line L9 (-217.5482, 3.7482) -> (-214.4891, 3.7482)
  line L10 (-217.5482, -1.3414) -> (-217.5482, 3.7482)
  circle C1 centre (-209.4687, -5.1844) radius 1.4
  arc A1 centre (-145.261, -34.4433) radius 69 clockwise from (-213.9733, -28.1494) to (-212.3934, -18.4984)
  arc A2 centre (-210.8341, -28.9906) radius 3.25 clockwise from (-213.7157, -30.4936) to (-213.9733, -28.1494)
  arc A3 centre (-212.2527, -29.7305) radius 1.65 clockwise from (-210.6589, -30.1576) to (-213.7157, -30.4936)
  arc A4 centre (-210.6418, -28.1617) radius 0.5 clockwise from (-210.5123, -27.6787) to (-210.1588, -28.2911)
  circle C2 centre (-209.4687, -5.1844) radius 3
  concentric C1 C2
  dimension "d1812" diameter C2 = 6
extrude "Extrude233" cut sketch "Sketch230" profile of C1 C2 along normal blind 10 and against normal blind 3
move_face "MoveFace351"
chamfer "Chamfer105" distance 1.6
fillet "Fillet273" radius 0.5
delete_face "DeleteFace180"
split "Split66" bodies "Furnish_R (1)"
split "Split67" bodies "Furnish_L (1)"
combine "Combine176" bodies "Furnish_R (1)"
combine "Combine177" bodies "Furnish_L (1)"
sketch "Sketch231" plane through (-12, 0, 0) normal (-1, 0, 0) x axis (0, -1, 0)
  line L1 (-152.7089, 8.4519) -> (-152.3198, 8.841)
  line L2 (-153.3679, 3.9459) -> (-153.3679, 6.8609)
  line L3 (-156.6179, 2.4459) -> (-154.8679, 2.4459)
  line L4 (-159.3679, 12.5) -> (-159.3679, 5.1959)
  line L5 (-102, 15.5) -> (-156.3679, 15.5)
  line L6 (-99.5, 12) -> (-99.5, 13)
  line L7 (-150.7288, 9.5) -> (-102, 9.5)
  line L8 (-169.5112, -33.2283) -> (-189.2884, -97.8715)
  curve K1 (-169.5112, -33.2283) -> (-143.7253, -13.6797)
  line L9 (-94.4207, -13.6797) -> (-143.7253, -13.6797)
  curve K2 (-94.4207, -13.6797) -> (-62.1781, 2.9716)
  curve K3 (-62.1781, 2.9716) -> (-62.1873, 4.4251)
  line L10 (-62.1873, 16) -> (-62.1873, 4.4251)
  line L11 (-205.8331, 16) -> (-62.1873, 16)
  line L12 (-221.2152, 0.6179) -> (-205.8331, 16)
  line L13 (-220.6993, -4.9724) -> (-221.2152, 0.6179)
  line L14 (-210.1488, -14.4679) -> (-220.6993, -4.9724)
  line L15 (-210.775, -33.2696) -> (-210.1488, -14.4679)
  line L16 (-237.9687, -92.3267) -> (-210.775, -33.2696)
  curve K4 (-237.8696, -92.8878) -> (-237, -95.0047)
  curve K5 (-237, -95.0047) -> (-238.046, -97.2764)
  curve K6 (-238.046, -97.2764) -> (-240.2199, -97.9919)
  line L17 (-242.9035, -103.0436) -> (-240.7107, -98.2815)
  line L18 (-239.2197, -106.4696) -> (-241.6185, -105.8082)
  curve K7 (-239.2197, -106.4696) -> (-240.3598, -109.3449)
  line L19 (-189.1188, -123.2274) -> (-240.3598, -109.3449)
  line L20 (-186.4094, -113.2266) -> (-189.1188, -123.2274)
  line L21 (-189.1513, -106.0289) -> (-186.4094, -113.2266)
  line L22 (-200, -50) -> (-190, -50)
  line L23 (-200, -30) -> (-200, -50)
  line L24 (-190, -30) -> (-200, -30)
  line L25 (-190, -50) -> (-190, -30)
  line L26 (-200, -30) -> (-190, -50)
  line L27 (-190, -30) -> (-200, -50)
  circle C1 centre (-71.0718, 1.1484) radius 3.5
  arc A1 centre (-150.7288, 7.25) radius 2.25 clockwise from (-152.3198, 8.841) to (-150.7288, 9.5)
  arc A2 centre (-151.1179, 6.8609) radius 2.25 clockwise from (-153.3679, 6.8609) to (-152.7089, 8.4519)
  arc A3 centre (-154.8679, 3.9459) radius 1.5 clockwise from (-153.3679, 3.9459) to (-154.8679, 2.4459)
  arc A4 centre (-156.6179, 5.1959) radius 2.75 clockwise from (-156.6179, 2.4459) to (-159.3679, 5.1959)
  arc A5 centre (-156.3679, 12.5) radius 3 clockwise from (-159.3679, 12.5) to (-156.3679, 15.5)
  arc A6 centre (-102, 13) radius 2.5 clockwise from (-102, 15.5) to (-99.5, 13)
  arc A7 centre (-102, 12) radius 2.5 clockwise from (-99.5, 12) to (-102, 9.5)
  circle C2 centre (-80, -5) radius 4.5
  arc A8 centre (-237.5145, -92.5358) radius 0.5 clockwise from (-237.8696, -92.8878) to (-237.9687, -92.3267)
  arc A9 centre (-240.2565, -98.4906) radius 0.5 clockwise from (-240.7107, -98.2815) to (-240.2199, -97.9919)
  arc A10 centre (-241.0868, -103.8801) radius 2 clockwise from (-241.6185, -105.8082) to (-242.9035, -103.0436)
  arc A11 centre (-177.9477, -101.7609) radius 11.9891 clockwise from (-189.1513, -106.0289) to (-189.2884, -97.8715)
  circle C3 centre (-209.4687, -5.1844) radius 3.5
  point P59 (-195, -40)
  point P57 (-200, -30)
  point P58 (-190, -30)
  point P55 (-190, -50)
  horizontal L22
  perpendicular L22 L23
  parallel L22 L24
  parallel L23 L25
  coincident L26 P59
  coincident L27 P59
  dimension "d1820" distance P57 P58 = 10
  dimension "d1821" distance P55 P58 = 20
extrude "Extrude234" new body sketch "Sketch231" profile of L22 L23 L24 L25 distance 1
mirror "Mirror51" mirrorStitchTolerance 0.1
combine "Combine178"
combine "Combine179"
combine "Combine180"
combine "Combine181"
sketch "Sketch232" plane through (-12, 0, 0) normal (-1, 0, 0) x axis (0, -1, 0)
  line L1 (-190, -50) -> (-190, -30)
  line L2 (-200, -50) -> (-190, -50)
  line L3 (-200, -30) -> (-200, -50)
  line L4 (-190, -30) -> (-200, -30)
  line L5 (-152.7089, 8.4519) -> (-152.3198, 8.841)
  line L6 (-153.3679, 3.9459) -> (-153.3679, 6.8609)
  line L7 (-156.6179, 2.4459) -> (-154.8679, 2.4459)
  line L8 (-159.3679, 12.5) -> (-159.3679, 5.1959)
  line L9 (-102, 15.5) -> (-156.3679, 15.5)
  line L10 (-99.5, 12) -> (-99.5, 13)
  line L11 (-150.7288, 9.5) -> (-102, 9.5)
  line L12 (-169.5112, -33.2283) -> (-189.2884, -97.8715)
  curve K1 (-169.5112, -33.2283) -> (-143.7253, -13.6797)
  line L13 (-94.4207, -13.6797) -> (-143.7253, -13.6797)
  curve K2 (-94.4207, -13.6797) -> (-62.1781, 2.9716)
  curve K3 (-62.1781, 2.9716) -> (-62.1873, 4.4251)
  line L14 (-62.1873, 16) -> (-62.1873, 4.4251)
  line L15 (-205.8331, 16) -> (-62.1873, 16)
  line L16 (-221.2152, 0.6179) -> (-205.8331, 16)
  line L17 (-220.6993, -4.9724) -> (-221.2152, 0.6179)
  line L18 (-210.1488, -14.4679) -> (-220.6993, -4.9724)
  line L19 (-210.775, -33.2696) -> (-210.1488, -14.4679)
  line L20 (-237.9687, -92.3267) -> (-210.775, -33.2696)
  curve K4 (-237.8696, -92.8878) -> (-237, -95.0047)
  curve K5 (-237, -95.0047) -> (-238.046, -97.2764)
  curve K6 (-238.046, -97.2764) -> (-240.2199, -97.9919)
  line L21 (-242.9035, -103.0436) -> (-240.7107, -98.2815)
  line L22 (-239.2197, -106.4696) -> (-241.6185, -105.8082)
  curve K7 (-239.2197, -106.4696) -> (-240.3598, -109.3449)
  line L23 (-189.1188, -123.2274) -> (-240.3598, -109.3449)
  line L24 (-186.4094, -113.2266) -> (-189.1188, -123.2274)
  line L25 (-189.1513, -106.0289) -> (-186.4094, -113.2266)
  line L26 (-199.85, -49.85) -> (-190.25, -49.85)
  line L27 (-199.85, -30.25) -> (-199.85, -49.85)
  line L28 (-190.25, -30.25) -> (-199.85, -30.25)
  line L29 (-190.25, -49.85) -> (-190.25, -30.25)
  line L30 (-199.85, -30.25) -> (-190.25, -49.85)
  line L31 (-190.25, -30.25) -> (-199.85, -49.85)
  circle C1 centre (-71.0718, 1.1484) radius 3.5
  arc A1 centre (-150.7288, 7.25) radius 2.25 clockwise from (-152.3198, 8.841) to (-150.7288, 9.5)
  arc A2 centre (-151.1179, 6.8609) radius 2.25 clockwise from (-153.3679, 6.8609) to (-152.7089, 8.4519)
  arc A3 centre (-154.8679, 3.9459) radius 1.5 clockwise from (-153.3679, 3.9459) to (-154.8679, 2.4459)
  arc A4 centre (-156.6179, 5.1959) radius 2.75 clockwise from (-156.6179, 2.4459) to (-159.3679, 5.1959)
  arc A5 centre (-156.3679, 12.5) radius 3 clockwise from (-159.3679, 12.5) to (-156.3679, 15.5)
  arc A6 centre (-102, 13) radius 2.5 clockwise from (-102, 15.5) to (-99.5, 13)
  arc A7 centre (-102, 12) radius 2.5 clockwise from (-99.5, 12) to (-102, 9.5)
  circle C2 centre (-80, -5) radius 4.5
  arc A8 centre (-237.5145, -92.5358) radius 0.5 clockwise from (-237.8696, -92.8878) to (-237.9687, -92.3267)
  arc A9 centre (-240.2565, -98.4906) radius 0.5 clockwise from (-240.7107, -98.2815) to (-240.2199, -97.9919)
  arc A10 centre (-241.0868, -103.8801) radius 2 clockwise from (-241.6185, -105.8082) to (-242.9035, -103.0436)
  arc A11 centre (-177.9477, -101.7609) radius 11.9891 clockwise from (-189.1513, -106.0289) to (-189.2884, -97.8715)
  circle C3 centre (-209.4687, -5.1844) radius 3.5
  point P63 (-195.05, -40.05)
  point P61 (-199.85, -30.25)
  point P62 (-190.25, -30.25)
  point P60 (-199.85, -49.85)
  horizontal L26
  perpendicular L26 L27
  parallel L26 L28
  parallel L27 L29
  coincident L30 P63
  coincident L31 P63
  dimension "d1826" distance P61 P62 = 9.6
  dimension "d1827" distance P60 P61 = 19.6
extrude "Extrude235" new body sketch "Sketch232" profile of L26 L27 L28 L29 distance 0.8 bodies "Joint piece_1"
remove_body "RemoveBody95"
copy_paste_bodies "CopyPasteBodies17"
remove_body "RemoveBody96"
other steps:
move "Move1"
split "Split1"
move "Move2"
move "Move3"
move "Move5"
move "Move3"
move "Move4"
base_feature "Base Feature1"
base_feature "Base Feature2"
base_feature "Base Feature3"
base_feature "Base Feature4" bodies "Barrel"
base_feature "Base Feature5" bodies "Clip bottom"
base_feature "Base Feature6"
move_face "MoveFace82"
base_feature "Base Feature8" bodies "PrimmBar"
base_feature "Base Feature9"
base_feature "Base Feature10" bodies "Angled Mini Talon extand"
base_feature "Base Feature11" bodies "Pusher"
base_feature "Base Feature12" bodies "Angled Mini Talon extand", "Angled Mini Talon extand (1)"
base_feature "Base Feature13" bodies "Core", "Core (1)"
base_feature "Base Feature14" bodies "Cover", "Cover (1)"
base_feature "Base Feature15"
base_feature "Base Feature16"
base_feature "Base Feature17" bodies "Joint piece_1", "Joint piece_2"
create_component "CreateComponent1"
create_component "CreateComponent2"
create_component "CreateComponent3"
create_component "CreateComponent4"
create_component "CreateComponent5"
create_component "CreateComponent6"
create_component "CreateComponent7"
create_component "CreateComponent8"
create_component "CreateComponent9"
create_component "CreateComponent10"
create_component "CreateComponent11"
create_component "CreateComponent12"
create_component "CreateComponent13"
create_component "CreateComponent14"
create_component "CreateComponent1"
create_component "CreateComponent2"
create_component "CreateComponent15"
create_component "CreateComponent16"
create_component "CreateComponent17"
create_component "CreateComponent18"
create_component "CreateComponent19"
create_component "CreateComponent1"
create_component "CreateComponent20"
create_component "CreateComponent21"
create_component "CreateComponent22"
create_component "CreateComponent23"
create_component "CreateComponent24"
create_component "CreateComponent25"
create_component "CreateComponent26"
create_component "CreateComponent27"
named bodies: "Gear 1", "Core", "Gear 2", "GripAft_R", "Trigger Pannel_R", "GripAft_L", "Trigger Pannel_L", "Grip plate_R", "Grip plate_L", "Trigger Gard", "Barrel", "Trigger_Pic_L", "Clip bottom", "Grip base", "PrimmBar", "Angled Mini Talon extand", "Pusher", "Barrel (1)", "Barrel (1) (1)", "Barrel (1) (1) (1)", "Barrel (2)", "Trigger Pannel_R (1)", "Trigger Pannel_L (1)", "GripAft_R (1)", "GripAft_L (1)", "Mag Release_R", "GripAft_L", "Hammer", "GripAft_L  (1)", "Mag Release_L", "Cover", "Safty Tip", "Prime_L", "Prime_top Plate", "Trigger Gard_Barrel", "Mag Release_R (1)", "Mag Release_R (2)", "Mag Release_L (1)", "Mag Release_L (2)", "Trigger Gard_Barrel (1)", "Trigger Gard_Barrel (3)", "Trigger Gard_Barrel (4)", "LockPin", "Prime_R (1)", "Prime_R (2)", "Prime_R (3)", "Prime_R (4)", "Prime_R (5)", "Prime_L (1)", "Prime_L (2)", "Prime_L (3)", "Prime_L (4)", "Prime_L (5)", "Prime_top Plate (1)", "Prime_top Plate (2)", "Handel Pin", "Trigger pin 1", "Trigger pin 2", "5mm pin_3", "5mm pin_4"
